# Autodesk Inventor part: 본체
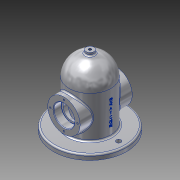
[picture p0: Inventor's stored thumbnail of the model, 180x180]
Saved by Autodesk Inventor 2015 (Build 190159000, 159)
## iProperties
Created: 2019-11
Part Number: 본체
Material: 알루미늄 6061
Document SubType Name: Modeling
Designer: Administrator
Density: 2.7 g/cm^3
Appearance: 알루미늄 - 평지
Mass: 1105.97 g
Surface Area: 883.585 cm^2
Volume: 409.62 cm^3
Author: Administrator
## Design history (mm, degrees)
sketch "스케치1"
  geometry: C1 r 40 at (0, 0); 1 further point
  constraints: 1 centre point, 1 coincident
  dimensions: "d0" = 80 diameter of C1
extrude "돌출1" new body sketch "스케치1" distance "d1" = 90; taper "d2" = 0 deg
sketch "스케치2"
  geometry: C1 r 70 at (0, 0); 1 further point
  constraints: 1 centre point, 1 coincident
  dimensions: "d3" = 140 diameter of C1
extrude "돌출2" join sketch "스케치2" distance "d4" = 10; taper "d5" = 0 deg
sketch "스케치3"
  geometry: L1 (0, -70)-(0, 70) reference; C1 r 31 at (50, 0); 1 further point
  constraints: 1 centre point
  dimensions: "d6" = 62 diameter of C1; "d7" = 50 distance of point (0, 0) C1.centre; "d8" = 50 distance from line of L1 C1.centre
extrude "돌출3" join sketch "스케치3" stored distance "d9" = 100; taper "d10" = 0 deg
sketch "스케치4"
  geometry: C1 r 30 at (0, 0); 1 further point
  constraints: 1 centre point, 1 coincident
  dimensions: "d11" = 60 diameter of C1
extrude "돌출4" cut sketch "스케치4" stored distance "d12" = 100; taper "d13" = 0 deg
sketch "스케치5"
  geometry: L1 (40, 40)-(-40, 40) reference; L2 (-40, -40)-(-40, 40) reference; C1 r 20 at (0, 0); 1 further point
  constraints: 1 centre point
  dimensions: "d14" = 40 diameter of C1; "d15" = 40 distance from line of L1 C1.centre; "d16" = 40 distance from line of L2 C1.centre
extrude "돌출5" cut sketch "스케치5" distance "d17" = 15; taper "d18" = 0 deg
sketch "스케치6"
  geometry: L1 (40, 40)-(-40, 40) reference; L2 (-40, -40)-(-40, 40) reference; C1 r 20 at (0, 0); 1 further point
  constraints: 1 centre point
  dimensions: "d19" = 40 diameter of C1; "d20" = 40 distance from line of L1 C1.centre; "d21" = 40 distance from line of L2 C1.centre
extrude "돌출6" cut sketch "스케치6" distance "d22" = 15; taper "d23" = 0 deg
sketch "스케치7"
  geometry: L1 (40, 40)-(-40, 40) reference; L2 (-40, -40)-(-40, 40) reference; C1 r 16.5 at (0, 0); 1 further point
  constraints: 1 centre point
  dimensions: "d24" = 33 diameter of C1; "d25" = 40 distance from line of L1 C1.centre; "d26" = 40 distance from line of L2 C1.centre
extrude "돌출7" cut sketch "스케치7" stored distance "d27" = 40 (= d25); taper "d28" = 0 deg
sketch "스케치8" dims "d29" = 52
  geometry: L1 (40, 40)-(-40, 40) reference; L2 (-40, -40)-(-40, 40) reference; 3 further points
  constraints: 1 vertical alignment, 2 other
  dimensions: "d30" = 14 distance from line of L1 point (0, 26); "d31" = 40 distance from line of L1 point (0, 0); "d32" = 40 distance from line of L2 point (0, 0)
hole "구멍1" sketch "스케치8" at (0, 26) diameter "d33" = 3.242; stored, may be unused: countersink angle "d37" = 90 deg, drill point angle "d39" = 118 deg; dims "d34" = 8, "d35" = 4, "d36" = 2, "d38" = 10
sketch "스케치9"
  geometry: L1 (90, 30)-(90, -30) reference; L2 (90, -40)-(90, 40) reference; L3 (90, 0)-(130, 0); L4 (90, 0)-(90, -40); A1 r 40 centre (90, 0) between (90, -40) and (130, 0); 1 further point
  constraints: 4 end point, 2 point on circle, 1 centre point, 1 perpendicular
  dimensions: "d43" = 40 radius of A1; "d44" = 130 distance of L3.end point (0, 0)
revolve "회전1" sketch "스케치9" stored, may be unused: angle "d45" = 90 deg
sketch "스케치10"
  geometry: L1 (90, 30)-(90, -30) reference; L2 (90, -40)-(90, 40) reference; L3 (120, 0)-(90, 0); L4 (90, 0)-(90, -30); A1 r 30 centre (90, 0) between (90, -30) and (120, 0); 1 further point
  constraints: 4 end point, 2 point on circle, 1 centre point, 1 horizontal
  dimensions: "d46" = 30 radius of A1; "d47" = 120 distance of point (0, 0) L3.start
revolve "회전2" sketch "스케치10" stored, may be unused: angle "d48" = 90 deg
sketch "스케치11"
  geometry: L1 (130, 0)-(135, 0); L2 (135, 0)-(135, -7.5); L3 (135, -7.5)-(126, -7.5); L4 (126, -7.5)-(126, 0); L5 (126, 0)-(130, 0); A1 r 40 centre (90, 0) between (90, -40) and (90, 40) reference; 1 further point
  constraints: 10 end point, 4 perpendicular, 1 horizontal, 1 point on circle, 1 point on line
  dimensions: "d49" = 5 distance of L1.start L1.end; "d50" = 7.5 distance of L1.end L2.end; "d51" = 9 distance of L2.end L3.end
revolve "회전3" sketch "스케치11" stored, may be unused: angle "d52" = 90 deg
sketch "스케치12"
  geometry: 2 further points
  constraints: 1 coincident
hole "구멍2" sketch "스케치12" at (0, 0) diameter "d53" = 5.188; stored, may be unused: countersink angle "d57" = 90 deg, drill point angle "d59" = 118 deg; dims "d54" = 12, "d55" = 4, "d56" = 2, "d58" = 16
node "작업 평면1"
sketch "스케치13"
  geometry: L1 (70, 0)-(-70, 0) reference; 2 further points
  constraints: 1 other
  dimensions: "d60" = 50 distance from line of L1 point (-0.152, 50)
feature "엠보싱1" sketch "스케치13" dims "d61" = 0.5, "d62" = 0
sketch "스케치14"
  geometry: C1 r 4.5 at (0, -55); C2 r 4.5 at (0, 55); A1 r 55 centre (0, 0) between (0, -55) and (0, 55); 1 further point
  constraints: 3 centre point, 2 point on circle, 1 coincident, 1 vertical alignment
  dimensions: "d63" = 110 diameter of A1; "d64" = 9 diameter of C1; "d65" = 9 diameter of C2; "d66" = 110 distance of C2.centre C1.centre
extrude "돌출8" cut sketch "스케치14" stored distance "d67" = 15; taper "d68" = 0 deg
fillet "모깎기1" dims "d69" = 0.3, "d70" = 3
chamfer "모따기1" distance "d71" = 1; stored, may be unused: second distance "d72" = 2, angle "d73" = 45 deg
node "솔리드1"
pattern_circular "원형 패턴1" dims angle "d41" = 360 deg
mirror "대칭1"
